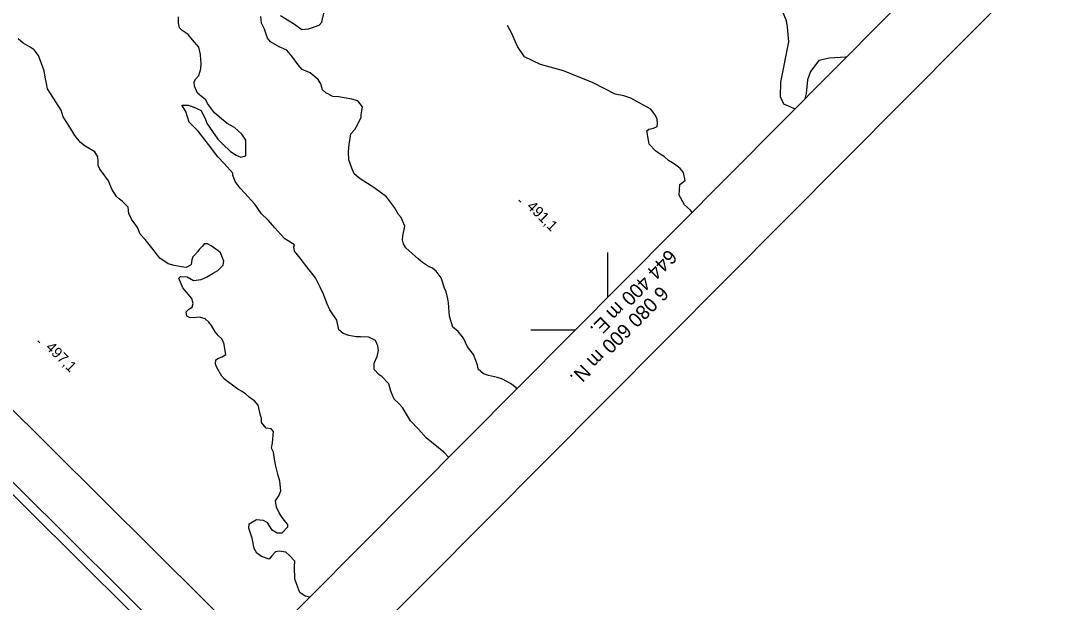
# Model space of a CAD drawing. Extents: x 642515 to 647219, y 6080136 to 6084356.
# Drawn here: x 644234.2 to 644528.9, y 6080523 to 6080687.3 of the extents above; entities that cross this region are included whole.
import ezdxf

# ---------------------------------------------------------------- set-up
doc = ezdxf.new("R2010")
doc.units = 0
for name, color, linetype in [('Level 1', 7, 'Continuous'), ('Level 2', 7, 'Continuous'), ('Level 3', 7, 'Continuous'), ('Level 60', 7, 'Continuous'), ('Level 61', 7, 'Continuous')]:
    doc.layers.add(name, color=color, linetype=linetype)

msp = doc.modelspace()

# ---------------------------------------------------------------- linework, layer by layer
at = {"layer": 'Level 1'}
for points in [[(644402.08, 6080666.57), (644395.81, 6080669.79), (644390, 6080672.15), (644387.51, 6080673.12), (644380.93, 6080674.94), (644376.42, 6080677.06), (644374.45, 6080680), (644372.74, 6080683.92), (644371.61, 6080685.92)], [(644423.81, 6080633.14), (644423.32, 6080633.74), (644421.61, 6080635.25), (644420.13, 6080638.05), (644420.33, 6080641.06), (644421.79, 6080642.2), (644421.32, 6080644.43), (644420.44, 6080645.51), (644419.5, 6080646.33), (644418.24, 6080647.14), (644417.14, 6080647.79), (644415.86, 6080648.92), (644414.76, 6080649.57), (644413.49, 6080650.53), (644411.66, 6080652.43), (644411.43, 6080653.55), (644411.01, 6080656.19), (644411.55, 6080656.62), (644412.9, 6080656.96), (644413.92, 6080657.43), (644414.03, 6080658.24), (644413.94, 6080659.53), (644413.47, 6080660.55), (644412.14, 6080662.32), (644409.04, 6080663.97), (644407.95, 6080664.62), (644406.52, 6080665.42), (644404.54, 6080666.09), (644402.08, 6080666.57)]]:
    msp.add_lwpolyline(points, dxfattribs=at)
at = {"layer": 'Level 2'}
for points in [[(644307.49, 6080688.74), (644311.18, 6080686.56), (644313.56, 6080684.79), (644315.4, 6080684.99), (644318.47, 6080686.08), (644319.22, 6080686.94), (644320.35, 6080691.85)], [(644289.82, 6080648.85), (644287.17, 6080652.37), (644284.26, 6080656.12), (644281.76, 6080658.61), (644280.76, 6080661.61), (644279.67, 6080663.47), (644281.45, 6080663.42), (644282.85, 6080662.95), (644285.09, 6080661.9), (644286.38, 6080659.41), (644286.79, 6080658.14), (644289.81, 6080653.84), (644291.19, 6080652.48), (644293.42, 6080650.37), (644295.03, 6080649.27), (644296.35, 6080648.72), (644297.77, 6080649.13), (644297.72, 6080653.56), (644296.64, 6080655.26), (644294.51, 6080657.13), (644292.5, 6080658.28), (644290.28, 6080660.07), (644288.92, 6080661.26), (644286.89, 6080663.95), (644286.42, 6080664.96), (644285.73, 6080665.56), (644284.12, 6080666.82), (644283.26, 6080668.78), (644283.18, 6080670.06), (644283.61, 6080670.89), (644284.43, 6080671.83), (644285.03, 6080673.73), (644285.17, 6080675.27), (644285.02, 6080676.3), (644284.93, 6080677.74), (644284.47, 6080679.81), (644282.71, 6080681.94), (644281.41, 6080683.39), (644279.72, 6080684.56), (644279.03, 6080685.32), (644278.77, 6080686.75), (644278.74, 6080688.44)], [(644374.31, 6080583.3), (644374.06, 6080583.59), (644372.53, 6080584.78), (644370.27, 6080586), (644368.78, 6080586.54), (644366.25, 6080587.1), (644364.84, 6080587.57), (644363.39, 6080588.84), (644363.15, 6080589.96), (644362.66, 6080591.3), (644362.06, 6080593.03), (644360.31, 6080595.17), (644359.26, 6080597.6), (644357.76, 6080599.52), (644356.23, 6080600.7), (644355.3, 6080603.79), (644354.97, 6080607.55), (644354.81, 6080608.75), (644354.28, 6080610.73), (644353.81, 6080611.75), (644352.89, 6080614.67), (644351.47, 6080616.51), (644350.45, 6080617.41), (644349.29, 6080617.82), (644347.6, 6080619), (644346.4, 6080620.05), (644344.77, 6080621.47), (644342.89, 6080623.12), (644342.25, 6080624.29), (644342.01, 6080625.4), (644342.1, 6080626.53), (644342.65, 6080629.23), (644341.6, 6080631.66), (644340.89, 6080632.58), (644339.71, 6080634.52), (644337.5, 6080637.52), (644335.64, 6080638.84), (644334.28, 6080639.88), (644333.1, 6080640.61), (644330.06, 6080642.66), (644328.36, 6080644), (644327.68, 6080645.65), (644326.88, 6080648.02), (644326.73, 6080650.27), (644326.92, 6080652.37), (644327.21, 6080654.09), (644327.44, 6080655.39), (644328.49, 6080656.59), (644329.3, 6080657.85), (644330.36, 6080660.1), (644330.31, 6080660.74), (644330.73, 6080662.95), (644329.33, 6080664.63), (644327.68, 6080665.17), (644325.56, 6080665.51), (644324.01, 6080665.81), (644322.31, 6080665.94), (644320.31, 6080666.93), (644319.36, 6080667.76), (644318.93, 6080669.5), (644318.2, 6080670.74), (644315.9, 6080672.61), (644313.66, 6080673.5), (644312.52, 6080674.8), (644310.75, 6080677.26), (644309.35, 6080678.94), (644307.18, 6080679.93), (644304.67, 6080681.37), (644303.88, 6080682.37), (644303.06, 6080684.89), (644302.14, 6080686.61), (644302.02, 6080688.53)], [(644452.92, 6080662.45), (644452.53, 6080662.47), (644449.7, 6080663.73), (644448.75, 6080665.78), (644448.8, 6080669.99), (644451.12, 6080681.3), (644450.69, 6080685.48), (644450.41, 6080687.24), (644449.33, 6080690)], [(644289.91, 6080622.33), (644287.97, 6080623.73), (644286.89, 6080624.22), (644286.01, 6080624.24), (644285.48, 6080623.64), (644284.59, 6080622.62), (644284.14, 6080622.11), (644283.32, 6080621.17), (644282.79, 6080620.57), (644282.52, 6080619.75), (644282.29, 6080618.45), (644282.07, 6080618.19), (644280.9, 6080617.55), (644279.6, 6080617.78), (644277.49, 6080618.13), (644275.77, 6080618.57), (644273.41, 6080620.19), (644271.2, 6080623.17), (644269.28, 6080625.46), (644267.9, 6080626.97), (644267.13, 6080628.85), (644265.44, 6080631.23), (644264.7, 6080632.79), (644264.49, 6080634.62), (644262.85, 6080636.36), (644262.09, 6080636.87), (644261.24, 6080637.62), (644259.9, 6080639.7), (644258.94, 6080642.05), (644257.17, 6080644.5), (644256.55, 6080645.34), (644256.08, 6080646.36), (644256.08, 6080647.56), (644255.99, 6080648.84), (644255.1, 6080650.23), (644252.33, 6080651.9), (644251.06, 6080652.86), (644249.49, 6080654.84), (644248.31, 6080656.77), (644247.33, 6080658.23), (644246.16, 6080660.17), (644245.55, 6080662.05), (644242.59, 6080666.76), (644241.77, 6080668.07), (644241.43, 6080669.58), (644241.07, 6080671.4), (644240.79, 6080673.15), (644239.14, 6080677.46), (644237.99, 6080679.07), (644236.82, 6080679.8), (644234.81, 6080680.95), (644233.44, 6080682.15)], [(644467.39, 6080677.02), (644467.11, 6080677.03), (644462.59, 6080676.73), (644459.56, 6080676.04), (644457.18, 6080672.97), (644456.36, 6080670.65), (644455.97, 6080666.74), (644455.66, 6080665.22)], [(644355.06, 6080563.91), (644353.66, 6080565.35), (644348.63, 6080569.44), (644346.54, 6080571.88), (644344.21, 6080574.22), (644341.95, 6080578.01), (644340.81, 6080579.31), (644339.62, 6080580.35), (644338.74, 6080582.63), (644338.12, 6080584.68), (644336.22, 6080586.65), (644335.29, 6080587.31), (644333.99, 6080588.75), (644334.03, 6080590.53), (644334.79, 6080592.43), (644335.24, 6080594.15), (644334.99, 6080595.42), (644334.33, 6080596.91), (644332.49, 6080597.91), (644330.15, 6080598), (644328.95, 6080598), (644326.83, 6080598.34), (644325.26, 6080598.96), (644323.99, 6080599.92), (644323.4, 6080602.7), (644321.43, 6080605.63), (644320.66, 6080607.51), (644319.69, 6080610.02), (644318.75, 6080612.05), (644317.38, 6080614.62), (644314.64, 6080618.22), (644313.14, 6080620.13), (644311.48, 6080622.19), (644311.32, 6080623.39), (644311.52, 6080623.97), (644311.02, 6080624.26), (644309.67, 6080625.13), (644308.75, 6080625.63), (644307.62, 6080626.93), (644305.89, 6080628.74), (644304.05, 6080630.96), (644302.16, 6080632.76), (644300.29, 6080635.46), (644297.34, 6080638.64), (644296.12, 6080640.01), (644294.71, 6080641.85), (644294.03, 6080643.65), (644294.07, 6080644.22), (644291.72, 6080646.88), (644289.82, 6080648.85)], [(644315.84, 6080524.42), (644314.47, 6080524.71), (644312.95, 6080525.73), (644311.58, 6080529.5), (644311.51, 6080533.03), (644311.56, 6080534.64), (644310.09, 6080536.23), (644309.06, 6080537.13), (644307.2, 6080537.4), (644306.16, 6080537.26), (644305.11, 6080536.06), (644304.29, 6080535.12), (644302.15, 6080535.94), (644300.88, 6080536.9), (644300.07, 6080538.22), (644299.56, 6080541.07), (644298.57, 6080543.9), (644298.73, 6080545.12), (644300.73, 6080546.38), (644302.68, 6080546.18), (644303.68, 6080545.61), (644305.02, 6080543.53), (644306.61, 6080542.59), (644307.98, 6080542.6), (644309.6, 6080544.28), (644309.63, 6080545), (644308.54, 6080546.17), (644307.83, 6080547.25), (644307.16, 6080548.29), (644306.37, 6080549.89), (644306.09, 6080551.64), (644307.04, 6080553.07), (644307.67, 6080554.47), (644307.33, 6080557.18), (644306.8, 6080559.16), (644306.25, 6080561.45), (644305.87, 6080563.44), (644305.59, 6080565.35), (644304.95, 6080566.51), (644305.25, 6080568.06), (644305.6, 6080571.21), (644304.91, 6080571.97), (644303.44, 6080572.2), (644302.13, 6080573.8), (644302.13, 6080575), (644301.92, 6080575.79), (644301.25, 6080578.64), (644300.2, 6080579.86), (644299.7, 6080580.22), (644298.68, 6080580.96), (644297.66, 6080581.86), (644296.56, 6080582.59), (644295.48, 6080583.24), (644294, 6080584.3), (644292.91, 6080585.04), (644291.75, 6080586.04), (644290.93, 6080586.91), (644289.52, 6080589.35), (644289.14, 6080590.29), (644289.3, 6080591.51), (644289.99, 6080591.95), (644291.09, 6080592.35), (644292.1, 6080592.98), (644291.55, 6080596.32), (644290.91, 6080597.48), (644289.98, 6080598.3), (644289.1, 6080599.37), (644288.01, 6080601.23), (644287.31, 6080602.14), (644286.29, 6080603.04), (644284.64, 6080603.57), (644282.97, 6080603.38), (644281.83, 6080603.47), (644281.09, 6080603.82), (644280.93, 6080605.01), (644281.6, 6080605.78), (644282.6, 6080606.41), (644282.86, 6080607.39), (644282.45, 6080608.81), (644279.99, 6080611.86), (644278.85, 6080614.52), (644279.3, 6080615.03), (644281.16, 6080614.91), (644282.99, 6080613.91), (644285.15, 6080614.14), (644286.63, 6080614.8), (644288.56, 6080615.97), (644289.8, 6080616.7), (644291.31, 6080618.24), (644291.55, 6080619.38), (644290.59, 6080621.73), (644289.91, 6080622.33)]]:
    msp.add_lwpolyline(points, dxfattribs=at)
at = {"layer": 'Level 3'}
for p, q in [((644374.87, 6080636.64), (644375.44, 6080636.08)), ((644238.97, 6080596.83), (644239.54, 6080596.27))]:
    msp.add_line(p, q, dxfattribs=at)
at = {"layer": 'Level 60'}
for p, q in [((644400, 6080609.17), (644400, 6080621.86)), ((644378.21, 6080600), (644390.81, 6080600))]:
    msp.add_line(p, q, dxfattribs=at)
for points in [[(643756.15, 6083509.1), (645893.11, 6081385.05), (644652.25, 6080135.58), (642514.75, 6082260.08)], [(642518.29, 6082260.09), (643756.16, 6083505.56), (645889.57, 6081385.04), (644651.74, 6080139.63)], [(643756.23, 6083485.06), (645517.55, 6081734.46), (644300.6, 6080509.08), (642538.79, 6082260.16)], [(645532.22, 6081719.89), (645869.07, 6081384.98), (644651.68, 6080160.13), (644314.78, 6080494.98)]]:
    msp.add_lwpolyline(points, close=True, dxfattribs=at)

# ---------------------------------------------------------------- texts
at = {"layer": 'Level 3'}
for s, p in [('491,1', (644376.89, 6080634.6)), ('497,1', (644241, 6080594.79))]:
    msp.add_text(s, height=3, rotation=315.59, dxfattribs=at).set_placement(p)
at = {"layer": 'Level 61'}
for s, p in [('644 400 m E.', (644417.1, 6080622.97)), ('6 080 600 m N.', (644414.73, 6080612.63))]:
    msp.add_text(s, height=4, rotation=225.175, dxfattribs=at).set_placement(p)

doc.saveas('drawing.dxf')
